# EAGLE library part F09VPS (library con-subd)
SUB-D
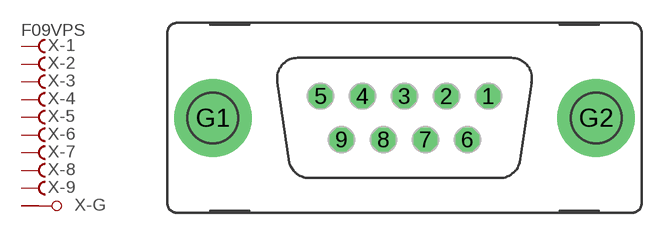
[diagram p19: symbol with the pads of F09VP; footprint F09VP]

Designator prefix X; gates -2=F -3=F -4=F -5=F -6=F -7=F -8=F -9=F -G=GND -1=FV

## F09VPS (OC_FARNELL: unknown; OC_NEWARK: unknown)  [F09VP]
1  -1:F  pas
2  -2:F  pas
3  -3:F  pas
4  -4:F  pas
5  -5:F  pas
6  -6:F  pas
7  -7:F  pas
8  -8:F  pas
9  -9:F  pas
G1  -G:G1  pas
G2  -G:G2  pas

## Footprint F09VP (pad centres in mm)
SUB-D
drill 1.016 octagon: 1 5.486,1.422; 2 2.743,1.422; 3 0,1.422; 4 -2.743,1.422; 5 -5.486,1.422; 6 4.115,-1.422; 7 1.372,-1.422; 8 -1.372,-1.422; 9 -4.115,-1.422
drill 3.302 pad 5.08 round: G1 -12.522,0; G2 12.522,0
